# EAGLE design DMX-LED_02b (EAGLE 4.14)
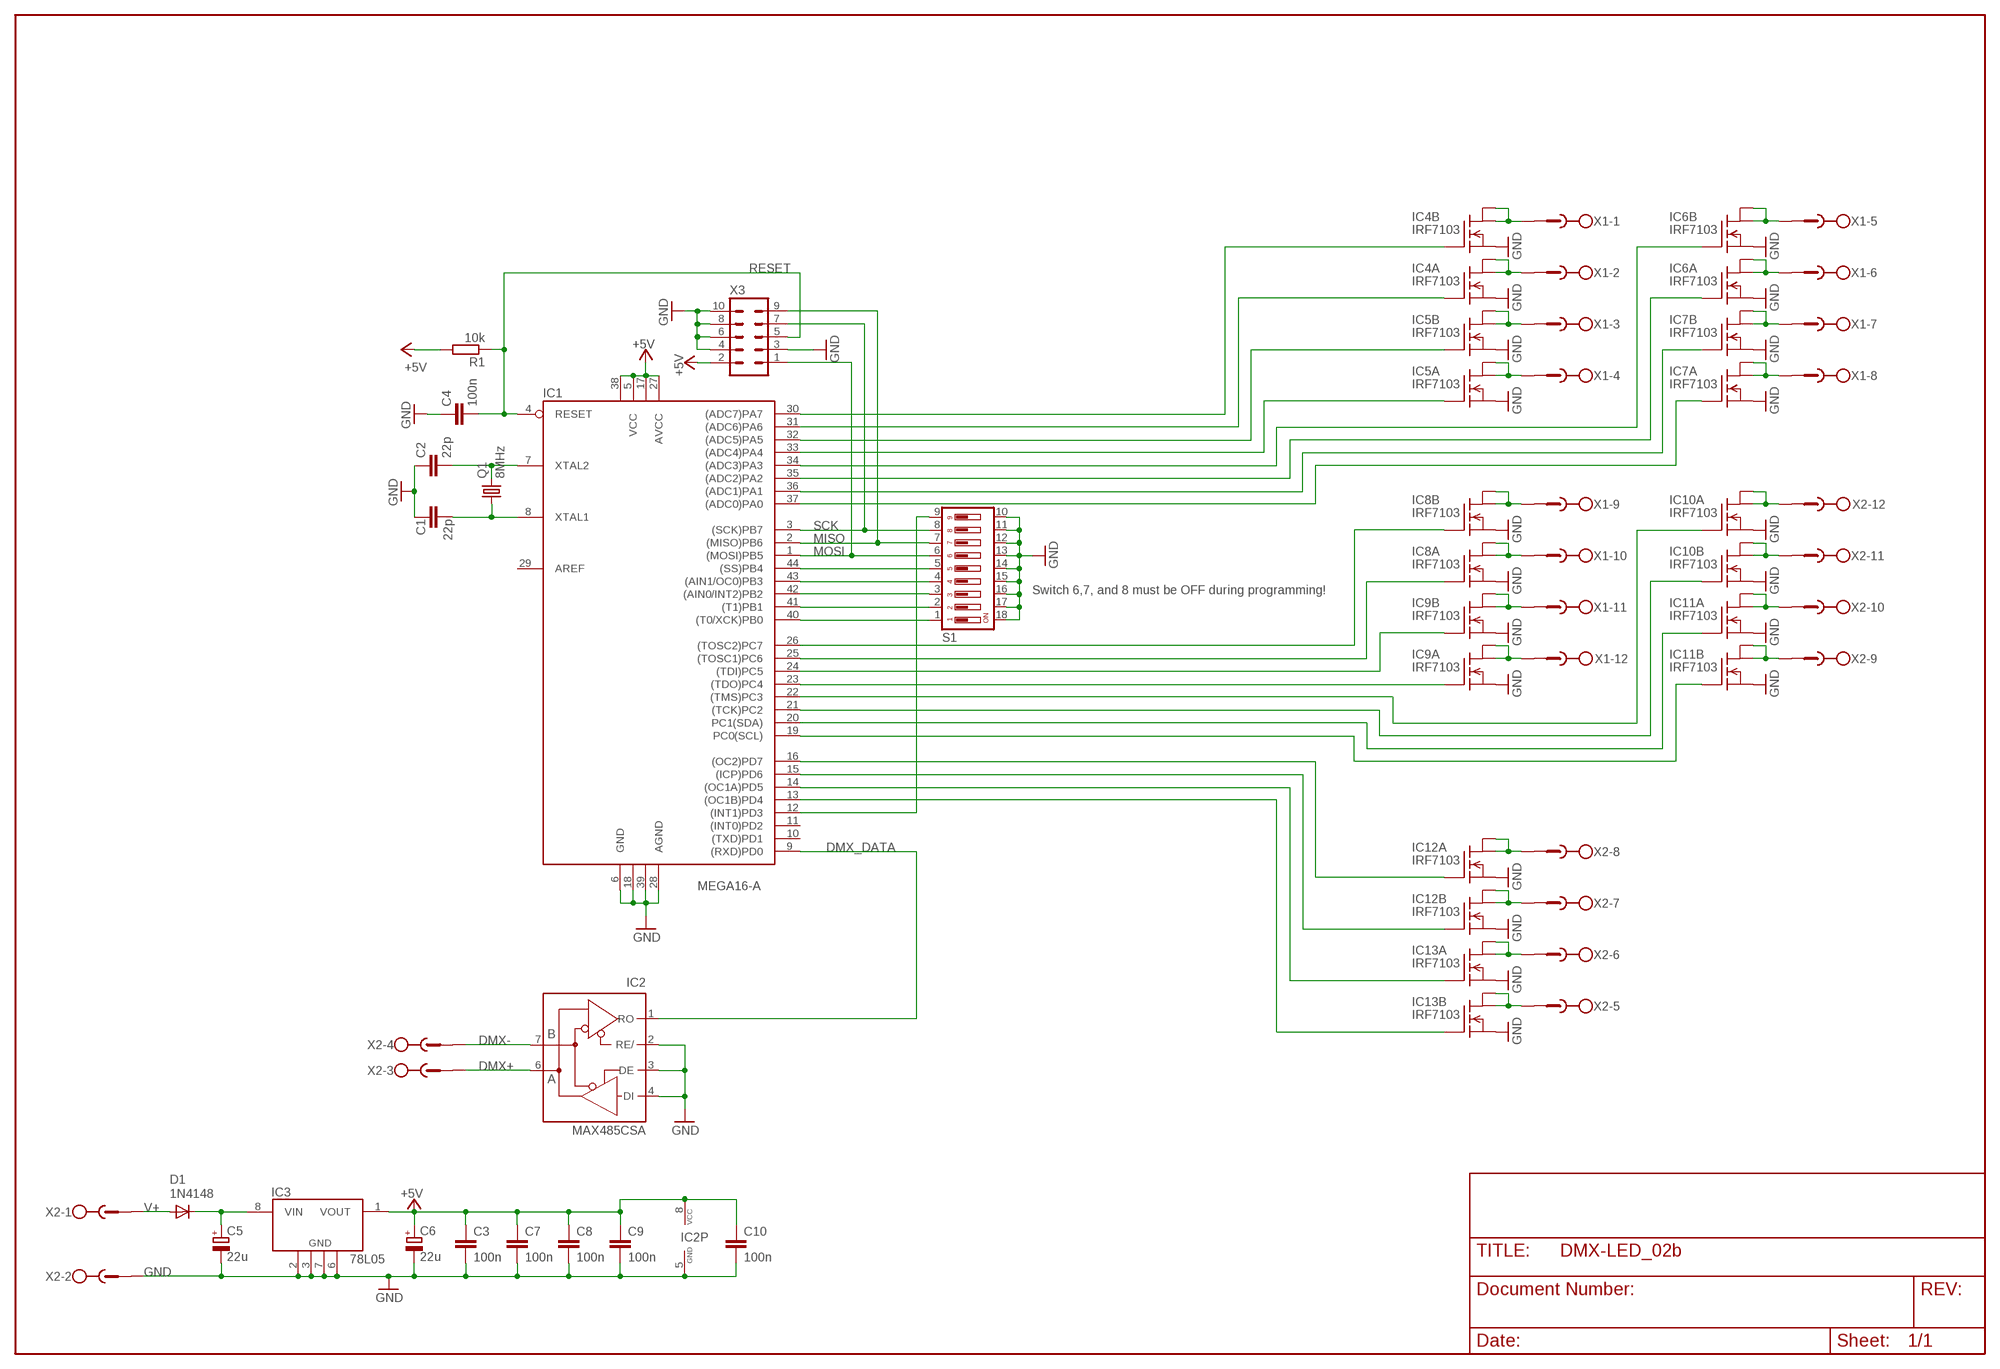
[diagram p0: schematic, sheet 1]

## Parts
C1  22p  C-EUC0805K  [C0805K]
C2  22p  C-EUC0805K  [C0805K]
C3  100n  C-EUC0805K  [C0805K]
C4  100n  C-EUC0805K  [C0805K]
C5  22u  CPOL-EUE2-5  [E2-5]
C6  22u  CPOL-EUE2-5  [E2-5]
C7  100n  C-EUC0805K  [C0805K]
C8  100n  C-EUC0805K  [C0805K]
C9  100n  C-EUC0805K  [C0805K]
C10  100n  C-EUC0805K  [C0805K]
D1  1N4148  DIODE-MINIMELF  [MINIMELF]
IC1  MEGA16-A  [TQFP44]
IC2  MAX485CSA  MAX481CSA  [SO08]
IC3  78L05  78LXX  [SO8]
IC4  IRF7103  [SO8]
IC5  IRF7103  [SO8]
IC6  IRF7103  [SO8]
IC7  IRF7103  [SO8]
IC8  IRF7103  [SO8]
IC9  IRF7103  [SO8]
IC10  IRF7103  [SO8]
IC11  IRF7103  [SO8]
IC12  IRF7103  [SO8]
IC13  IRF7103  [SO8]
Q1  8MHz  CRYTALHC49S  [HC49/S]
R1  10k  R-EU_M0805  [M0805]
S1  DIP09YL  [DIP09YL]
X1  MSTBV12  [MSTBV12]
X2  MSTBV12  [MSTBV12]
X3  ML10  [ML10]

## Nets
+5V: C3.1 C6.+ C7.1 C8.1 C9.1 C10.1 IC1.5(VCC) IC1.17(VCC1) IC1.27(AVCC) IC1.38(VCC2) IC2.8(VCC) IC3.1(VOUT) R1.2 X3.2
DMX+: IC2.6(A) X2.3
DMX-: IC2.7(B) X2.4
DMX_DATA: IC1.9((RXD)PD0) IC2.1(RO)
GND: C1.1 C2.1 C3.2 C4.1 C5.- C6.- C7.2 C8.2 C9.2 C10.2 IC1.6(GND) IC1.18(GND1) IC1.28(AGND) IC1.39(GND2) IC2.2(RE/) IC2.3(DE) IC2.4(DI) IC2.5(GND) IC3.2(GND1) IC3.3(GND2) IC3.6(GND4) IC3.7(GND3) IC4.1(A:S) IC4.3(B:S) IC5.1(A:S) IC5.3(B:S) IC6.1(A:S) IC6.3(B:S) IC7.1(A:S) IC7.3(B:S) IC8.1(A:S) IC8.3(B:S) IC9.1(A:S) IC9.3(B:S) IC10.1(A:S) IC10.3(B:S) IC11.1(A:S) IC11.3(B:S) IC12.1(A:S) IC12.3(B:S) IC13.1(A:S) IC13.3(B:S) S1.10 S1.11 S1.12 S1.13 S1.14 S1.15 S1.16 S1.17 S1.18 X2.2 X3.3 X3.4 X3.6 X3.8 X3.10
MISO: IC1.2((MISO)PB6) S1.7 X3.9
MOSI: IC1.1((MOSI)PB5) S1.6 X3.1
N$1: IC1.30((ADC7)PA7) IC4.4(B:G)
N$5: IC1.44((SS)PB4) S1.5
N$6: C5.+ D1.C IC3.8(VIN)
N$7: IC1.43((AIN1/OC0)PB3) S1.4
N$8: IC1.41((T1)PB1) S1.2
N$9: IC1.12((INT1)PD3) S1.9
N$10: IC1.31((ADC6)PA6) IC4.2(A:G)
N$11: IC4.7(A:D) IC4.8(A:D) X1.2
N$12: IC1.40((T0/XCK)PB0) S1.1
N$13: IC4.5(B:D) IC4.6(B:D) X1.1
N$14: IC1.32((ADC5)PA5) IC5.4(B:G)
N$15: IC1.33((ADC4)PA4) IC5.2(A:G)
N$16: IC5.5(B:D) IC5.6(B:D) X1.3
N$17: IC5.7(A:D) IC5.8(A:D) X1.4
N$18: IC6.5(B:D) IC6.6(B:D) X1.5
N$19: IC6.7(A:D) IC6.8(A:D) X1.6
N$20: IC7.5(B:D) IC7.6(B:D) X1.7
N$21: IC7.7(A:D) IC7.8(A:D) X1.8
N$22: IC1.34((ADC3)PA3) IC6.4(B:G)
N$23: IC1.35((ADC2)PA2) IC6.2(A:G)
N$24: IC1.36((ADC1)PA1) IC7.4(B:G)
N$25: IC1.37((ADC0)PA0) IC7.2(A:G)
N$26: IC1.26((TOSC2)PC7) IC8.4(B:G)
N$27: IC1.25((TOSC1)PC6) IC8.2(A:G)
N$28: IC1.42((AIN0/INT2)PB2) S1.3
N$29: IC1.24((TDI)PC5) IC9.4(B:G)
N$30: IC1.23((TDO)PC4) IC9.2(A:G)
N$31: IC1.22((TMS)PC3) IC10.2(A:G)
N$32: IC1.21((TCK)PC2) IC10.4(B:G)
N$33: IC1.20(PC1(SDA)) IC11.2(A:G)
N$34: IC1.19(PC0(SCL)) IC11.4(B:G)
N$35: IC8.5(B:D) IC8.6(B:D) X1.9
N$36: IC8.7(A:D) IC8.8(A:D) X1.10
N$37: IC9.5(B:D) IC9.6(B:D) X1.11
N$38: IC9.7(A:D) IC9.8(A:D) X1.12
N$39: IC10.7(A:D) IC10.8(A:D) X2.12
N$40: IC10.5(B:D) IC10.6(B:D) X2.11
N$41: IC11.7(A:D) IC11.8(A:D) X2.10
N$42: IC11.5(B:D) IC11.6(B:D) X2.9
N$43: IC1.16((OC2)PD7) IC12.2(A:G)
N$44: IC1.15((ICP)PD6) IC12.4(B:G)
N$45: IC1.14((OC1A)PD5) IC13.2(A:G)
N$46: IC1.13((OC1B)PD4) IC13.4(B:G)
N$47: IC12.7(A:D) IC12.8(A:D) X2.8
N$48: IC12.5(B:D) IC12.6(B:D) X2.7
N$49: IC13.7(A:D) IC13.8(A:D) X2.6
N$50: IC13.5(B:D) IC13.6(B:D) X2.5
RESET: C4.2 IC1.4(RESET) R1.1 X3.5
SCK: IC1.3((SCK)PB7) S1.8 X3.7
V+: D1.A X2.1
XTAL1: C1.2 IC1.8(XTAL1) Q1.1
XTAL2: C2.2 IC1.7(XTAL2) Q1.2
Unconnected: IC1.10((TXD)PD1) IC1.11((INT0)PD2)

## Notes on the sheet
- Switch 6,7, and 8 must be OFF during programming!

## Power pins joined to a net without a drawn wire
AREF: IC1.29(AREF)

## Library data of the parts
C1-C4 C7-C10 = rcl:C-EU: CAPACITOR, European symbol
C5 C6 = rcl:CPOL-EU: POLARIZED CAPACITOR, European symbol
D1 = diode:DIODE-: DIODE
IC1 = atmel:MEGA16: MICROCONTROLLER 16 Kbytes FLASH 1 kbytes SRAM 512 bytes EEPROM USART 8-channel 10 bit ADC
IC2 = maxim:MAX481CSA: RS485 TRANSEIVER
IC3 = selfmade:78LXX
IC4-IC13 = selfmade:IRF7103
Q1 = crystal:CRYTAL: CRYSTAL
R1 = rcl:R-EU_: RESISTOR, European symbol
S1 = switch-dil:DIP09YL: DIL/CODE SWITCH
X1 X2 = con-phoenix-500:MSTBV12: PHOENIX
X3 = con-harting-ml:ML10: HARTING

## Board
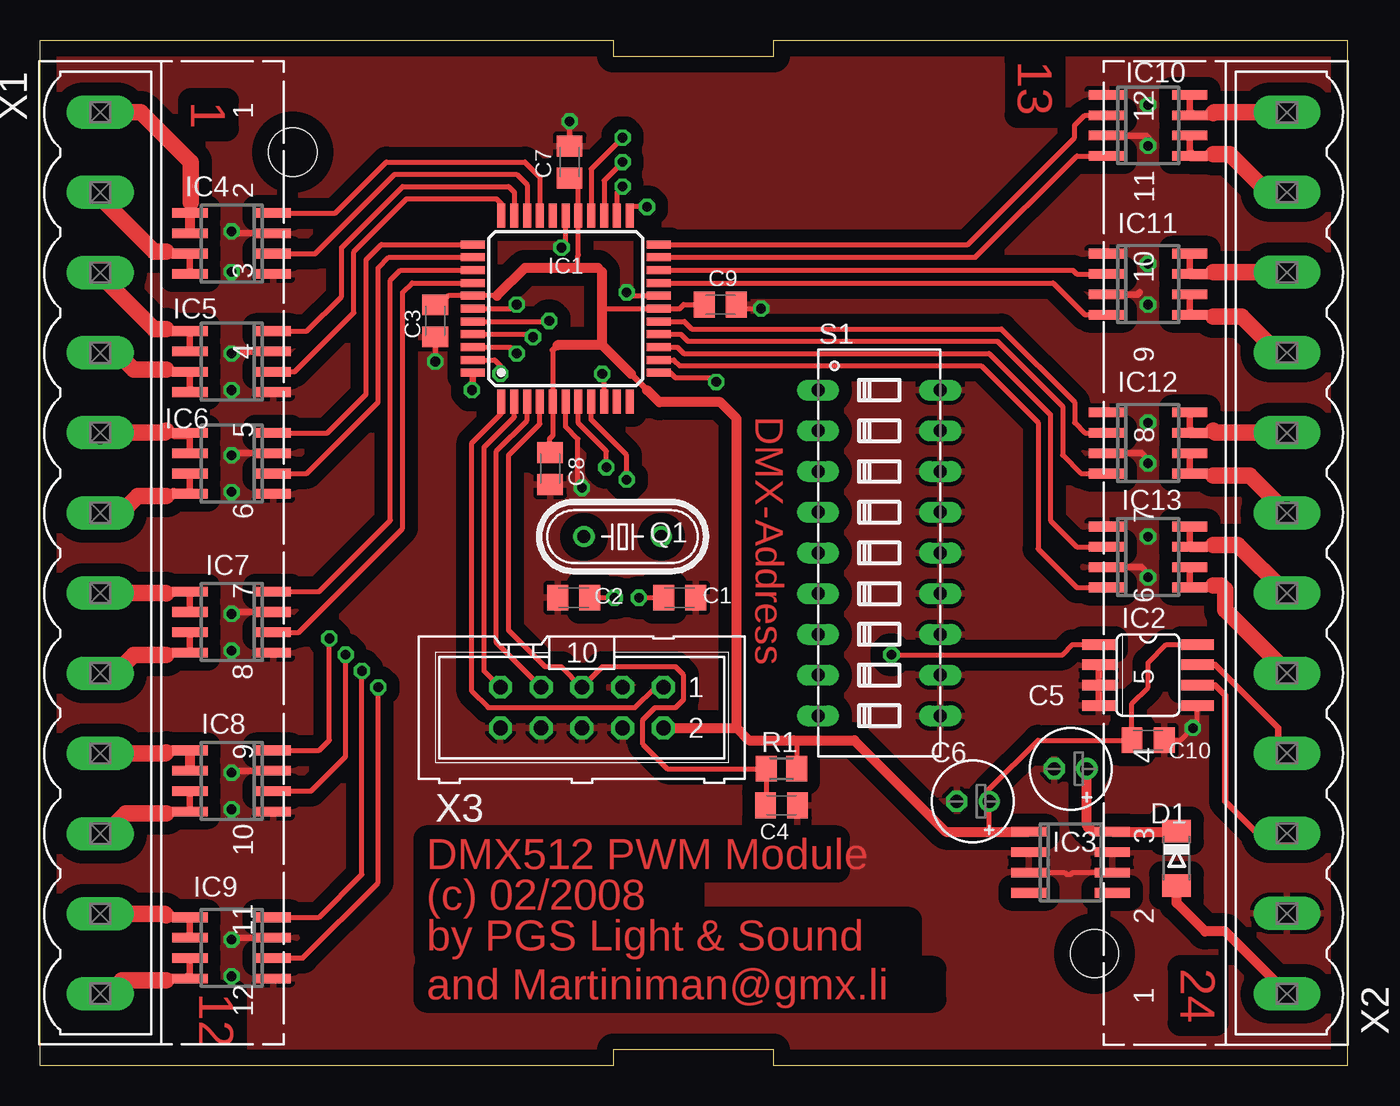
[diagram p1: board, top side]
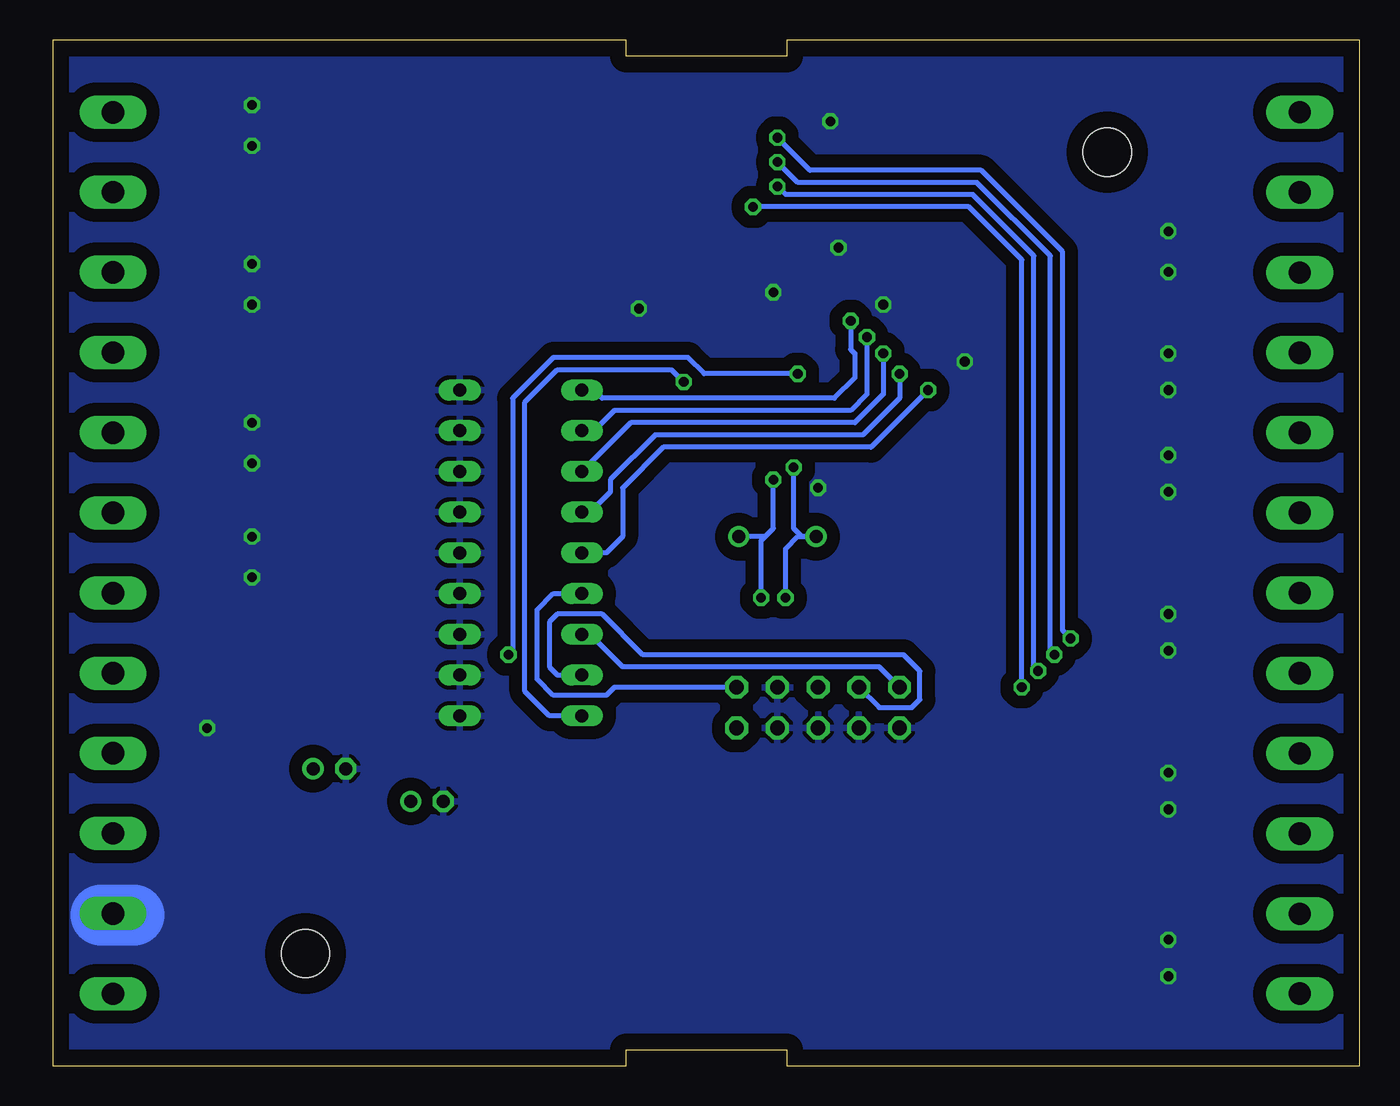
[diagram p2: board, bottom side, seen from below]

Size 81.5 x 64 mm. Coordinates in mm from the lower left corner, seen from the top.
Outline: 0,64 35.75,64 35.75,63 45.75,63 45.75,64 81.5,64 81.5,0 45.75,0 45.75,1 35.75,1 35.75,0 0,0 0,64
Copper layers (1*16): Top 0.035mm / dielectric 1.5mm / Bottom 0.035mm
Design rules "default": minimum track width 10mil, minimum drill 0.6mm, track to track 12mil, track to pad 12mil, pad to pad 10mil, via to via 12mil, smd to smd 8mil, copper to edge 40mil, drill to drill 8mil, minimum pad ring 10mil, minimum via ring 8mil, stop-mask expansion 4mil, vias tented up to drill 0mil, thermal gap 10mil
Holes 3 mm at 15.75,57 65.75,7

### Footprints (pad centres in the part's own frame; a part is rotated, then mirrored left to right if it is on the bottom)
C0805K = smd 1.3 x 1.6: 1 -1,0; 2 1,0
E2-5 = drill 0.813 pad 1.27 round: + -1.016,0 | drill 0.813 pad 1.27 octagon: - 1.016,0
MINIMELF = smd 1.4 x 1.8: A 1.7,0; C -1.7,0
TQFP44 = smd 1.5 x 0.5: 1 -5.8,4; 2 -5.8,3.2; 3 -5.8,2.4; 4 -5.8,1.6; 5 -5.8,0.8; 6 -5.8,0; 7 -5.8,-0.8; 8 -5.8,-1.6; 9 -5.8,-2.4; 10 -5.8,-3.2; 11 -5.8,-4; 23 5.8,-4; 24 5.8,-3.2; 25 5.8,-2.4; 26 5.8,-1.6; 27 5.8,-0.8; 28 5.8,0; 29 5.8,0.8; 30 5.8,1.6; 31 5.8,2.4; 32 5.8,3.2; 33 5.8,4 | smd 0.5 x 1.5: 12 -4,-5.8; 13 -3.2,-5.8; 14 -2.4,-5.8; 15 -1.6,-5.8; 16 -0.8,-5.8; 17 0,-5.8; 18 0.8,-5.8; 19 1.6,-5.8; 20 2.4,-5.8; 21 3.2,-5.8; 22 4,-5.8; 34 4,5.8; 35 3.2,5.8; 36 2.4,5.8; 37 1.6,5.8; 38 0.8,5.8; 39 0,5.8; 40 -0.8,5.8; 41 -1.6,5.8; 42 -2.4,5.8; 43 -3.2,5.8; 44 -4,5.8
SO08 = smd 0.66 x 2.032: 1 -1.905,-3.073; 2 -0.635,-3.073; 3 0.635,-3.073; 4 1.905,-3.073; 5 1.905,3.073; 6 0.635,3.073; 7 -0.635,3.073; 8 -1.905,3.073
SO8 = smd 0.6 x 2.2: 1 -1.905,-2.6; 2 -0.635,-2.6; 3 0.635,-2.6; 4 1.905,-2.6; 5 1.905,2.6; 6 0.635,2.6; 7 -0.635,2.6; 8 -1.905,2.6
HC49/S = drill 0.813 round: 1 -2.413,0; 2 2.413,0
M0805 = smd 1.3 x 1.6: 1 -0.95,0; 2 0.95,0
DIP09YL = drill 0.813 long: 1 -10.16,-3.81; 2 -7.62,-3.81; 3 -5.08,-3.81; 4 -2.54,-3.81; 5 0,-3.81; 6 2.54,-3.81; 7 5.08,-3.81; 8 7.62,-3.81; 9 10.16,-3.81; 10 10.16,3.81; 11 7.62,3.81; 12 5.08,3.81; 13 2.54,3.81; 14 0,3.81; 15 -2.54,3.81; 16 -5.08,3.81; 17 -7.62,3.81; 18 -10.16,3.81
MSTBV12 = drill 1.397 long: 1 -27.5,0; 2 -22.496,0; 3 -17.492,0; 4 -12.489,0; 5 -7.51,0; 6 -2.506,0; 7 2.497,0; 8 7.501,0; 9 12.505,0; 10 17.509,0; 11 22.513,0; 12 27.491,0
ML10 = drill 0.914 octagon: 1 -5.08,-1.27; 2 -5.08,1.27; 3 -2.54,-1.27; 4 -2.54,1.27; 5 0,-1.27; 6 0,1.27; 7 2.54,-1.27; 8 2.54,1.27; 9 5.08,-1.27; 10 5.08,1.27

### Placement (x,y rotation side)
C1  39.88,29.21 180 top
C2  33.28,29.21 0 top
C3  24.64,46.48 270 top
C4  46.23,16.26 180 top
C5  64.27,18.54 180 top
C6  58.17,16.51 180 top
C7  33.02,56.39 90 top
C8  31.81,37.27 270 top
C9  42.42,47.5 0 top
C10  69.09,20.32 0 top
D1  70.87,12.95 270 top
IC1  32.77,47.24 90 top
IC2  69.09,24.38 270 top
IC3  64.27,12.7 270 top
IC4  11.94,51.31 90 top
IC5  11.94,43.94 90 top
IC6  11.94,37.59 90 top
IC7  11.94,27.69 90 top
IC8  11.94,17.78 90 top
IC9  11.94,7.37 90 top
IC10  69.09,58.67 270 top
IC11  69.09,48.77 270 top
IC12  69.09,38.86 270 top
IC13  69.09,31.75 270 top
Q1  36.33,33.02 180 top
R1  46.23,18.54 0 top
S1  52.33,32 270 top
X1  3.75,32 270 top
X2  77.75,32 90 top
X3  33.79,22.35 180 top

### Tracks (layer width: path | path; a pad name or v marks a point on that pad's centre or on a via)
+5V
  Top 0.305: 35.06,47.24 IC1.17 39.88,47.24 40.14,47.5 C9.1 | 31.97,44.67 IC1.5 31.97,39.33 31.75,39.12 31.75,38.1 31.81,38.15 C8.1 | C3.1 24.88,47.48 25.44,48.04 IC1.38 28.49,48.04 | C7.1 33.02,55.37 33.57,54.83 IC1.27 33.57,50.58 33.53,50.55 33.53,49.78 | 35.06,44.96 35.06,45.21 | 35.06,49.53 34.8,49.78 | IC2.8 70.23,26.29 69.09,25.15 69.09,23.62 68.08,22.61 68.08,20.32 C10.1 62.23,20.32 59.19,17.27 C6.+ 59.19,14.61 | R1.2 47.18,20.13 46.99,20.32
  Top 0.406: 37.85,42.16 36.83,43.18 | 32.26,44.96 31.97,44.67
  Top 0.61: 32.26,44.96 35.06,44.96 36.83,43.18 | 35.06,45.21 35.06,47.24 35.06,49.53 | 34.8,49.78 33.53,49.78 30.23,49.78 28.49,48.04 | X3.2 43.44,21.08 | 43.44,21.08 44.2,20.32 46.99,20.32 50.77,20.32 56.49,14.61 59.19,14.61 IC3.1 | 43.44,21.08 43.44,40.39 42.42,41.4 38.61,41.4 37.85,42.16
DMX+
  Top 0.406: IC2.6 73.28,23.75 73.92,23.11 73.92,16.51 75.7,14.73 76.71,14.73 76.97,14.48 77,14.51 X2.3
DMX-
  Top 0.406: IC2.7 73.28,25.02 77.22,21.08 77.22,19.81 77.52,19.51 X2.4
DMX_DATA  (via drill 0.6)
  Top 0.305: IC1.9 35.17,43.07 v35.06,43.18 | v53.09,25.65 63.76,25.65 64.39,26.29 IC2.1
  Bottom 0.305: v35.06,43.18 40.9,43.18 41.91,44.2 50.3,44.2 52.84,41.66 52.84,25.91 v53.09,25.65
GND  (via drill 0.6)
  Top 0.305: IC1.39 29.47,47.24 v29.72,47.5 | IC1.28 32.77,51.31 v32.52,51.05 | C3.2 v24.64,43.94 | C7.2 v33.02,58.93 | C10.2 71.12,20.32 v71.89,21.08 72.14,21.08 72.17,21.11 IC2.5 | IC3.6 64.39,12.06 64.27,11.94 64.01,11.94 63.89,12.06 IC3.3 | C9.2 43.44,47.5 43.69,47.24 v44.96,47.24 | IC1.18 36.8,48.04 v36.58,48.26 | IC1.6 32.77,39.88 33.53,39.12 33.53,36.32
  Top 0.406: IC2.2 66.02,23.9 66.04,23.88 66.02,23.85 IC2.3 66.02,22.63 66.04,22.61 66.02,22.58 IC2.4 | IC7.3 12.32,28.32 12.2,28.45 | IC4.3 12.07,51.94 11.94,51.82 | IC6.3 12.07,38.23 v11.94,38.1 | IC8.3 12.32,18.41 12.2,18.29 | IC9.3 12.32,8 12.2,7.87 | IC5.3 12.32,44.58 12.2,44.7 | IC13.3 68.71,31.11 68.84,30.99 | IC12.3 68.71,38.23 68.84,38.1 | IC11.3 68.46,48.13 68.58,48.26 | IC10.3 68.97,58.04 69.09,57.91
  Bottom 3.81: 76.46,9.4 78.49,9.4
  other vias: 11.94,52.07 11.94,49.53 11.94,44.45 11.94,42.16 11.94,35.81 11.94,28.19 11.94,25.91 11.94,18.29 11.94,16 11.94,7.87 11.94,5.59 69.09,59.94 69.09,57.4 69.09,50.04 69.09,47.5 69.09,40.13 69.09,37.59 69.09,33.02 69.09,30.48 33.79,36.07
  pour Bottom (isolate 0.813): -0.25,64.01 81.03,64.01 81.03,0 -0.25,0
  pour Top (isolate 0.813): -0.25,64.01 81.28,64.01 81.28,0 -0.25,0
MISO
  Top 0.305: IC1.2 29.57,40.49 27.69,38.61 27.69,24.64 X3.9
  Bottom 0.305: X3.9 29.98,24.89 45.98,24.89 48.01,26.92 S1.7
MOSI
  Top 0.305: IC1.1 28.77,40.7 26.93,38.86 26.93,23.37 27.94,22.35 37.09,22.35 38.36,23.62 X3.1
  Bottom 0.305: X3.1 46.49,23.62 46.99,23.11 50.3,23.11 51.31,24.13 51.31,28.45 50.3,29.46 S1.6
N$1
  Top 0.305: IC1.30 31.17,55.45 30.23,56.39 21.59,56.39 18.42,53.21 IC4.4
N$5  (via drill 0.6)
  Top 0.406: IC1.44 26.97,42.21 v26.93,42.16
  Bottom 0.305: v26.93,42.16 30.48,38.61 43.44,38.61 45.98,36.07 45.98,33.02 46.99,32 S1.5
N$6
  Top 0.406: 65.66,14.61 IC3.8
  Top 0.61: C5.+ 65.28,14.99 65.66,14.61 | D1.C 70.79,14.65 70.62,14.48 70.49,14.61 IC3.8
N$7  (via drill 0.6)
  Top 0.305: IC1.43 28.35,44.04 28.71,43.69 v28.71,43.18
  Bottom 0.305: v28.71,43.18 28.71,41.66 30.99,39.37 43.95,39.37 46.74,36.58 46.74,35.81 48.01,34.54 S1.4
N$8  (via drill 0.6)
  Top 0.305: IC1.41 30.56,45.64 v30.74,45.47
  Bottom 0.305: v30.74,45.47 30.74,41.91 31.75,40.89 46.49,40.89 47.76,39.62 S1.2
N$9  (via drill 0.6)
  Top 0.305: IC1.12 39.31,43.24 39.63,42.93 41.91,42.93 v42.17,42.67
  Bottom 0.305: S1.9 50.55,21.84 52.07,23.37 52.07,41.4 50.04,43.43 42.93,43.43 v42.17,42.67
N$10
  Top 0.305: IC1.31 30.37,54.98 29.72,55.63 22.1,55.63 17.15,50.67 IC4.2
N$11
  Top 0.406: IC4.8 9.34,49.47 9.4,49.53 9.34,49.59 IC4.7
  Top 0.61: 7.88,50.8 8.13,50.8 8.26,50.67 IC4.7
  Top 1.016: X1.2 3.75,54.17 7.12,50.8 7.88,50.8
N$12  (via drill 0.6)
  Top 0.305: IC1.40 31.72,46.44 v31.75,46.48
  Bottom 0.305: v31.75,46.48 31.75,44.7 31.5,44.45 31.5,42.93 32.77,41.66 47.25,41.66 47.76,42.16 S1.1
N$13
  Top 0.61: 9.4,53.85 9.4,53.59 9.34,53.53 IC4.5 9.34,53.15 9.4,53.09 9.34,53.03 IC4.6
  Top 1.016: X1.1 6.29,59.5 9.4,56.39 9.4,53.85
N$14
  Top 0.305: IC1.32 29.57,54.51 29.21,54.86 22.61,54.86 18.8,51.05 18.8,48.01 16.64,45.85 IC5.4
N$15
  Top 0.305: IC5.2 15.88,43.31 19.56,46.99 19.56,50.8 22.86,54.1 28.45,54.1 28.77,53.78 IC1.33
N$16
  Top 0.406: IC5.5 9.34,45.78 9.4,45.72 9.34,45.66 IC5.6
  Top 0.61: IC5.5 8.01,45.85 7.88,45.97
  Top 1.016: X1.3 3.75,49.34 7.12,45.97 7.88,45.97
N$17
  Top 0.406: IC5.7 9.34,43.24 9.4,43.18 9.34,43.12 IC5.8
  Top 0.61: 7.88,43.43 8.13,43.43 8.26,43.31 IC5.7
  Top 1.016: X1.4 4.79,44.49 5.85,43.43 7.88,43.43
N$18
  Top 0.406: IC6.5 9.34,39.43 9.4,39.37 9.34,39.31 IC6.6
  Top 0.61: 7.88,39.62 8.13,39.62 8.33,39.43 9.34,39.43
  Top 1.016: X1.5 7.76,39.51 7.88,39.62
N$19
  Top 0.406: IC6.8 9.34,35.75 9.4,35.81 9.34,35.87 IC6.7
  Top 0.61: 7.88,35.56 8.13,35.56 8.33,35.75 9.34,35.75
  Top 1.016: X1.6 5.05,34.51 6.1,35.56 7.88,35.56
N$20
  Top 0.406: IC7.5 9.34,29.52 9.4,29.46 9.34,29.4 IC7.6
  Top 0.61: 7.88,29.46 8.13,29.46 8.26,29.59 IC7.5
  Top 1.016: X1.7 7.84,29.5 7.88,29.46
N$21
  Top 0.406: IC7.7 9.34,26.98 9.4,26.92 9.34,26.86 IC7.8
  Top 0.61: 7.88,25.65 8.13,25.65 8.26,25.78 IC7.8
  Top 1.016: X1.8 4.69,24.5 5.85,25.65 7.88,25.65
N$22
  Top 0.305: IC1.34 21.28,51.24 20.32,50.29 20.32,41.91 17.91,39.5 IC6.4
N$23
  Top 0.305: IC1.35 21.75,50.44 21.09,49.78 21.09,41.4 16.64,36.96 IC6.2
N$24
  Top 0.305: IC1.36 22.47,49.64 21.85,49.02 21.85,34.04 17.4,29.59 IC7.4
N$25
  Top 0.305: IC1.37 23.19,48.84 22.61,48.26 22.61,33.53 16.13,27.05 IC7.2
N$26  (via drill 0.6)
  Top 0.305: IC8.4 17.4,19.68 18.04,20.32 v18.04,26.67 | IC1.26 34.37,55.96 v36.33,57.91
  Bottom 0.305: v36.33,57.91 34.29,55.88 23.63,55.88 18.55,50.8 18.55,27.18 v18.04,26.67
N$27  (via drill 0.6)
  Top 0.305: IC8.2 16.89,17.14 19.05,19.3 v19.05,25.65 | IC1.25 35.17,55.23 v36.33,56.39
  Bottom 0.305: v36.33,56.39 35.06,55.12 23.88,55.12 19.31,50.55 19.31,25.91 v19.05,25.65
N$28  (via drill 0.6)
  Top 0.305: IC1.42 29.33,44.84 v29.72,44.45
  Bottom 0.305: v29.72,44.45 29.72,41.91 31.5,40.13 45.47,40.13 S1.3
N$29  (via drill 0.6)
  Top 0.305: IC9.4 17.4,9.27 20.07,11.94 v20.07,24.64 | IC1.24 35.97,54.51 v36.33,54.86
  Bottom 0.305: v36.33,54.86 35.82,54.36 24.13,54.36 20.32,50.55 20.32,24.89 v20.07,24.64
N$30  (via drill 0.6)
  Top 0.305: IC9.2 16.39,6.73 21.09,11.43 v21.09,23.62 | IC1.23 36.77,53.53 36.83,53.59 v37.85,53.59
  Bottom 0.305: v21.09,23.62 21.09,50.29 24.39,53.59 v37.85,53.59
N$31
  Top 0.305: IC1.22 57.85,51.24 64.52,57.91 64.52,58.67 65.16,59.31 IC10.2
N$32
  Top 0.305: IC1.21 58.32,50.44 64.65,56.77 IC10.4
N$33
  Top 0.305: IC1.20 64.41,49.64 64.65,49.4 IC11.2
N$34
  Top 0.305: IC1.19 63.17,48.84 65.16,46.86 IC11.4
N$35
  Top 0.61: 7.88,19.56 8.13,19.56 8.26,19.68 IC8.5 9.34,19.62 9.4,19.56 9.34,19.5 IC8.6
  Top 1.016: X1.9 7.81,19.5 7.88,19.56
N$36
  Top 0.406: IC8.7 9.34,17.08 9.4,17.02 9.34,16.96 IC8.8
  Top 0.61: 7.88,15.75 8.13,15.75 8.26,15.88 IC8.8
  Top 1.016: X1.10 4.08,14.49 5.34,15.75 7.88,15.75
N$37
  Top 0.406: IC9.5 9.34,9.2 9.4,9.14 9.34,9.08 IC9.6
  Top 0.61: 7.88,9.4 8.13,9.4 8.26,9.27 IC9.5
  Top 1.016: X1.11 7.79,9.49 7.88,9.4
N$38
  Top 0.406: IC9.8 9.28,5.46 9.15,5.59 9.34,5.78 IC9.7
  Top 0.61: IC9.8 8.01,5.46 7.88,5.33
  Top 1.016: X1.12 4.26,4.51 5.08,5.33 7.88,5.33
N$39
  Top 0.406: IC10.7 71.76,59.31 71.89,59.44 71.69,59.63 IC10.8
  Top 0.61: IC10.7 73.03,59.31 73.16,59.44
  Top 1.016: X2.12 73.21,59.49 73.16,59.44
N$40
  Top 0.406: IC10.5 71.76,56.77 71.89,56.9 71.69,57.09 IC10.6
  Top 0.61: 73.16,56.9 72.9,56.9 72.78,56.77 IC10.5
  Top 1.016: X2.11 76.56,54.51 74.17,56.9 73.16,56.9
N$41
  Top 0.406: IC11.7 71.69,49.47 71.63,49.53 71.69,49.59 IC11.8
  Top 0.61: IC11.7 73.03,49.4 73.16,49.53
  Top 1.016: X2.10 73.18,49.51 73.16,49.53
N$42
  Top 0.406: IC11.5 71.69,46.93 71.63,46.99 71.69,47.05 IC11.6
  Top 0.61: IC11.5 73.03,46.86 73.16,46.74
  Top 1.016: X2.9 77.17,44.51 74.93,46.74 73.16,46.74
N$43
  Top 0.305: IC1.16 40.17,46.44 40.64,45.97 59.95,45.97 64.52,41.4 64.52,40.13 65.16,39.5 IC12.2
N$44
  Top 0.305: IC1.15 39.96,45.64 40.39,45.21 59.69,45.21 63.76,41.15 63.76,38.1 64.9,36.96 IC12.4
N$45
  Top 0.305: IC1.14 39.74,44.84 40.14,44.45 59.19,44.45 63,40.64 63,34.04 64.65,32.38 IC13.2
N$46
  Top 0.305: IC1.13 39.53,44.04 39.88,43.69 58.68,43.69 62.23,40.13 62.23,32.26 64.65,29.84 IC13.4
N$47
  Top 0.406: IC12.7 71.76,39.5 71.89,39.62 71.69,39.82 IC12.8
  Top 0.61: IC12.7 73.03,39.5 73.16,39.62
  Top 1.016: X2.8 73.28,39.5 73.16,39.62
N$48
  Top 0.406: IC12.5 71.69,37.02 71.63,37.08 71.69,37.14 IC12.6
  Top 0.61: 73.16,36.83 72.9,36.83 72.78,36.96 IC12.5
  Top 1.016: X2.7 77.75,34.52 75.44,36.83 73.16,36.83
N$49
  Top 0.406: IC13.7 71.69,32.45 71.63,32.51 71.69,32.57 IC13.8
  Top 0.61: 73.16,32.51 72.9,32.51 72.78,32.38 IC13.7
  Top 1.016: X2.6 77.7,29.49 74.68,32.51 73.16,32.51
N$50
  Top 0.406: 72.01,29.84 IC13.5 71.69,29.91 71.63,29.97 71.69,30.03 IC13.6
  Top 0.61: IC13.5 73.03,29.84 73.16,29.97
  Top 1.016: 73.16,29.97 73.66,29.97 73.92,29.72 73.92,28.45 77.75,24.62 X2.5
RESET
  Top 0.305: IC1.4 31.17,40.06 29.21,38.1 29.21,27.18 31.5,24.89 32.52,24.89 X3.5 35.06,24.89 39.63,24.89 40.14,24.38 40.14,22.86 39.63,22.35 38.36,22.35 37.6,21.59 37.6,20.07 39.12,18.54 R1.1 45.28,16.32 45.22,16.26 C4.2
SCK
  Top 0.305: IC1.3 30.37,40.27 28.45,38.35 28.45,26.42 X3.7
  Bottom 0.305: X3.7 29.98,22.35 27.94,22.35 27.44,22.86 27.44,24.64 28.45,25.65 44.71,25.65 47.25,28.19 50.04,28.19 50.55,27.69 50.55,24.89 50.04,24.38 S1.8
V+
  Top 0.61: D1.A 70.87,10.16 72.65,8.38 73.92,8.38 77.75,4.55 X2.1
XTAL1  (via drill 0.6)
  Top 0.305: IC1.8 34.37,40.31 36.58,38.1 v36.58,36.58 | v37.34,29.21 C1.2
  Bottom 0.305: 37.09,33.02 Q1.1 | 37.09,33.02 36.58,33.53 v36.58,36.58 | 37.09,33.02 37.22,32.89 | v37.34,29.21 37.34,32.77 37.09,33.02
XTAL2  (via drill 0.6)
  Top 0.305: C2.2 v35.82,29.21 | IC1.7 33.57,40.09 35.31,38.35 v35.31,37.34
  Bottom 0.305: v35.31,37.34 35.31,33.53 34.8,33.02 Q1.2 | Q1.2 34.04,33.02 | Q1.2 35.06,33.02 35.82,32.26 v35.82,29.21

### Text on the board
Top: 13 | 1 | DMX-Address | DMX512 PWM Module | (c) 02/2008 | by PGS Light & Sound | 24 | 12 | and Martiniman@gmx.li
